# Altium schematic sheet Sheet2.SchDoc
size A; SheetNumber: 1; SheetTotal: 1
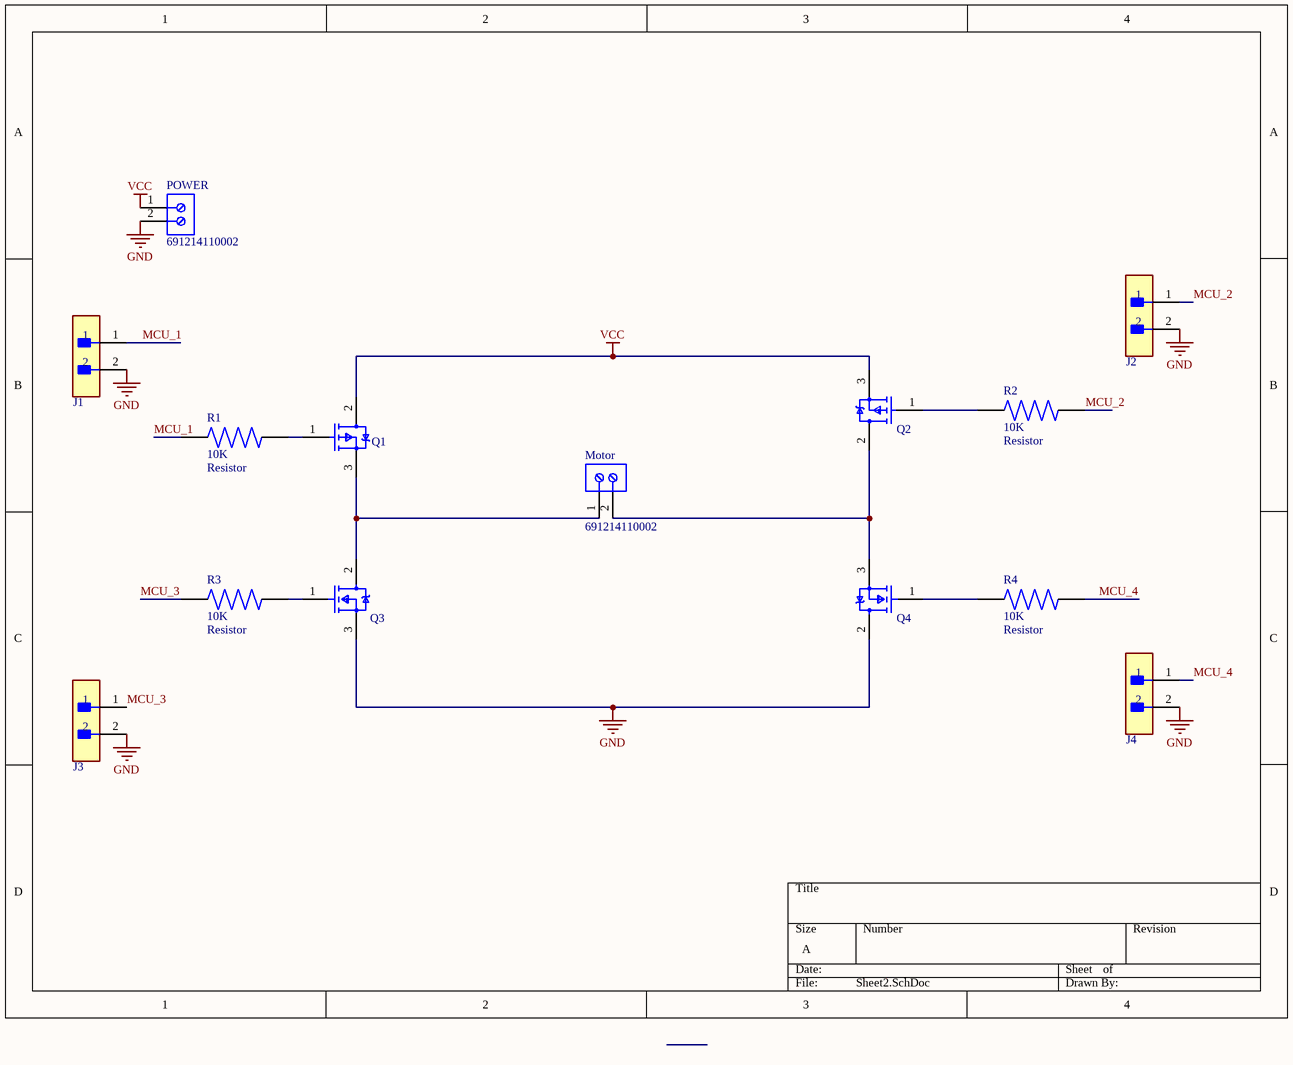
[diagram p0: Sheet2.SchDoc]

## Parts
J1  B2B-XH-A(LF)(SN)  [JST Connector]  (value not drawn)
J2  B2B-XH-A(LF)(SN)  [JST Connector]  (value not drawn)
J3  B2B-XH-A(LF)(SN)  [JST Connector]  (value not drawn)
J4  B2B-XH-A(LF)(SN)  [JST Connector]  (value not drawn)
Motor  691214110002  [Terminal block]
POWER  691214110002  [Terminal block]
Q1  IRF4905PBF  [Mosfet P-Ch]  (value not drawn)
Q2  IRF4905PBF  [Mosfet P-Ch]  (value not drawn)
Q3  IRLZ44NPbF  [MOSFET N-CH 55V 47A TO220AB]  (value not drawn)
Q4  IRLZ44NPbF  [MOSFET N-CH 55V 47A TO220AB]  (value not drawn)
R1  Resistor  value 10K  [Resistor]
R2  Resistor  value 10K  [Resistor]
R3  Resistor  value 10K  [Resistor]
R4  Resistor  value 10K  [Resistor]

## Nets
GND: J1.2 J2.2 J3.2 J4.2 POWER.2 Q3.3(S) Q4.2(D)
VCC: POWER.1 Q1.2(DRAIN) Q2.3(SOURCE)
MCU_1: J1.1 R1.1
MCU_2: J2.1 R2.2
MCU_3: J3.1 R3.1
MCU_4: J4.1 R4.2
NetMotor_1: Motor.1 Q1.3(SOURCE) Q3.2(D)
NetMotor_2: Motor.2 Q2.2(DRAIN) Q4.3(S)
NetQ1_1: Q1.1(GATE) R1.2
NetQ2_1: Q2.1(GATE) R2.1
NetQ3_1: Q3.1(G) R3.2
NetQ4_1: Q4.1(G) R4.1

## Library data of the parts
J1-J4 = jst connector: CONN HEADER VERT 2POS 2.5MM; Current Rating: 3A; Voltage Rating: 250V; Number of Contacts: 2; Contact Resistance: 20mR; Wire/Cable Gauge: 22AWG; Insulation Resistance: 1GR; Connector Type: Male Pin
Motor POWER = Terminal block: NexarPartId: 18818288; Plating: Brass, Steel; Current: 10A; Pitch: 3.5052mm; Number of Levels: 1; Number of Contacts: 2; Wire Gauge (Min): 16AWG; Voltage: 300V; Wire Gauge (Max): 24AWG; Stripping Length: -6mm
Q1 Q2 = Mosfet P-CH: MOSFET P-CH 55V 74A TO-220AB; Drain to Source Resistance: 20mR; Input Capacitance: 3.4nF; Max Dual Supply Voltage: -55V; Power Dissipation: 200W; Turn-On Delay Time: 18ns; Element Configuration: Single; Threshold Voltage: -4V; Gate to Source Voltage (Vgs): 20V; Turn-Off Delay Time: 61ns
Q3 Q4 = MOSFET N-CH 55V 47A TO220AB: Continuous Drain Current (ID): 47A; Turn-On Delay Time: 11ns; Gate to Source Voltage (Vgs): 16V; Element Configuration: Single; Rds On Max: 22mR; Turn-Off Delay Time: 26ns; Max Power Dissipation: 110W; Threshold Voltage: 2V; Drain to Source Voltage (Vdss): 55V; Drain to Source Resistance: 35mR; Input Capacitance: 1.7nF
R1-R4 = Resistor: 10.2 kOhms Â±1% 0.25W, 1/4W Through Hole Resistor Axial - Metal Film; MF: Yageo; MP: MFR-25FBF52-10K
